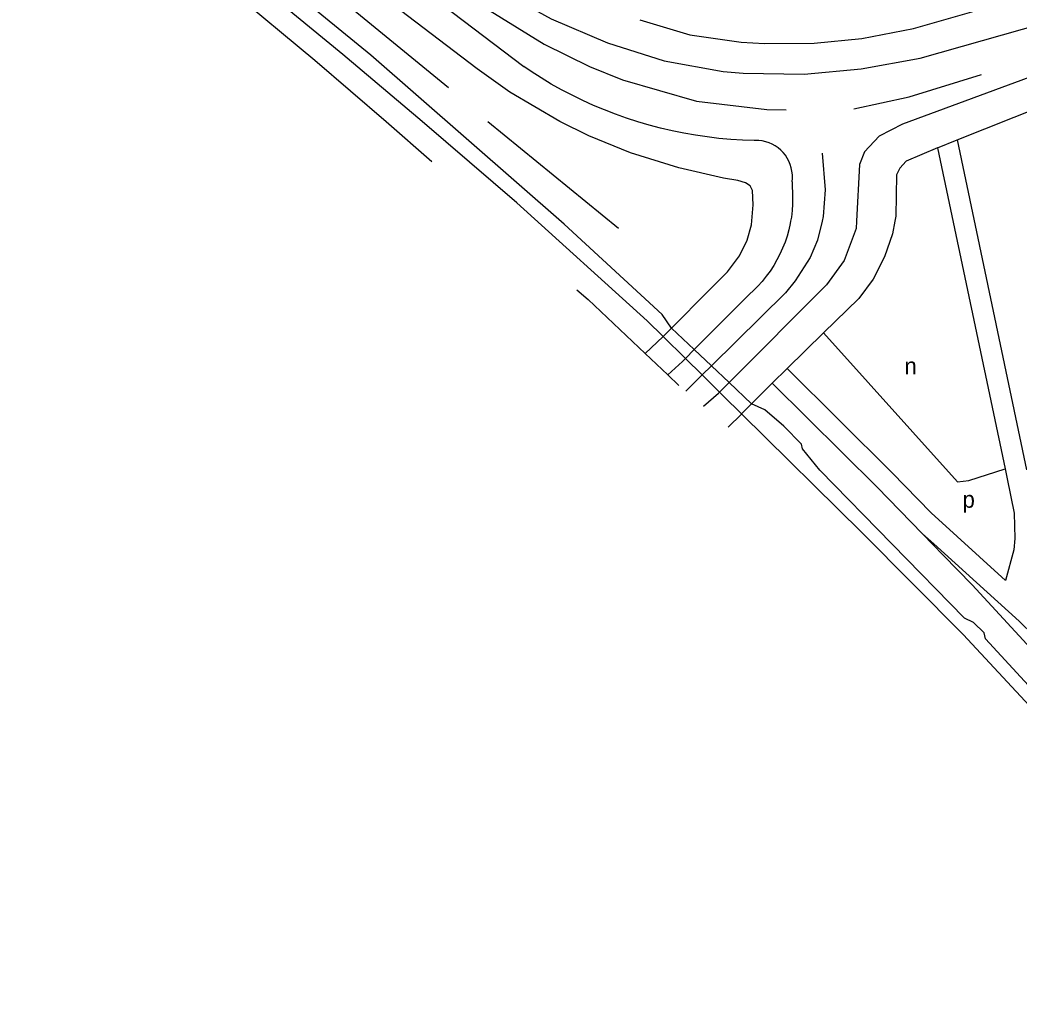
# Model space of a CAD drawing. Extents: x 163026 to 166241, y 382475 to 384501.
# Drawn here: x 164331.2 to 164570.9, y 383286.9 to 383524.4 of the extents above; entities that cross this region are included whole.
import ezdxf

# ---------------------------------------------------------------- set-up
doc = ezdxf.new("R2010")
doc.units = 0
for name, color, linetype in [('BLT_Basislijn', 7, 'Continuous'), ('BLT_Centroide', 7, 'Continuous'), ('BLT_Spoorlijn', 7, 'Continuous')]:
    doc.layers.add(name, color=color, linetype=linetype)

msp = doc.modelspace()

# ---------------------------------------------------------------- linework, layer by layer
at = {"layer": 'BLT_Basislijn'}
for p, q in [((164298.69, 383629.84), (164452.06, 383513.21)), ((164372.19, 383558.79), (164434.06, 383508.15)), ((164556.06, 383495.63), (164581.85, 383505.92)), ((164443.45, 383499.99), (164474.81, 383474.42)), ((164551.35, 383493.75), (164556.06, 383495.63)), ((164516.46, 383485.59), (164516.59, 383481.78)), ((164506.29, 383458.66), (164492.98, 383445.34)), ((164485.51, 383448.49), (164487.56, 383450.47)), ((164487.56, 383450.47), (164492.98, 383445.34)), ((164481.24, 383444.37), (164485.51, 383448.49)), ((164481.16, 383444.29), (164481.24, 383444.37)), ((164492.98, 383445.34), (164490.85, 383443.21)), ((164492.98, 383445.34), (164497.11, 383441.43)), ((164490.13, 383442.48), (164486.64, 383439.26)), ((164490.85, 383443.21), (164490.13, 383442.48)), ((164497.11, 383441.43), (164494.88, 383439.24)), ((164497.11, 383441.43), (164501.36, 383437.41)), ((164486.57, 383439.19), (164486.62, 383439.25)), ((164486.64, 383439.26), (164486.62, 383439.25)), ((164491.04, 383435.45), (164494.39, 383438.76)), ((164494.88, 383439.24), (164494.39, 383438.76)), ((164501.36, 383437.41), (164499.07, 383435.1)), ((164501.36, 383437.41), (164506.74, 383432.32)), ((164511.69, 383437.3), (164510.92, 383436.55)), ((164490.94, 383435.36), (164491.04, 383435.45)), ((164495.23, 383431.72), (164498.84, 383434.87)), ((164499.07, 383435.1), (164498.84, 383434.87)), ((164506.74, 383432.32), (164510.92, 383436.55)), ((164504.35, 383429.9), (164506.74, 383432.32)), ((164501.12, 383426.72), (164504.32, 383429.87)), ((164504.32, 383429.87), (164504.35, 383429.9)), ((164568.06, 383414.31), (164569.76, 383406.1)), ((164549.85, 383406.17), (164567.69, 383389.93))]:
    msp.add_line(p, q, dxfattribs=at)
for points in [[(164487.56, 383450.47), (164485.27, 383453.7), (164461.77, 383475.44), (164415.36, 383515.97), (164364.92, 383557.15), (164327.9, 383585.54), (164282.31, 383618.56), (164259.41, 383634.23), (164211.65, 383666.06), (164167.61, 383692.96), (164167.28, 383695.05), (164154.4, 383702.67), (164152.43, 383702), (164109.02, 383726.87), (164060.25, 383752.65), (163978.72, 383792.41), (163915.23, 383819.71), (163854.36, 383843.93), (163797.39, 383864.74), (163783.25, 383869.74), (163782.14, 383872.57), (163761.29, 383879.43), (163759.17, 383880.76)], [(164316.74, 383637.52), (164399.59, 383569.15), (164439.68, 383536.44), (164449.09, 383529.98), (164458.65, 383524.65), (164472.19, 383518.92), (164485.74, 383514.54), (164499.92, 383512), (164504.7, 383511.64), (164519.36, 383511.35), (164533, 383512.62), (164547.18, 383515.25), (164581.89, 383525.04), (164642.18, 383547.36), (164693.59, 383567.42), (164700, 383570.19), (164761.7, 383597.42), (164778.75, 383605.71), (164783.1, 383609.13), (164785.13, 383612.46), (164785.97, 383614.66), (164786.37, 383617.55)], [(164487.56, 383450.47), (164496.42, 383459.44), (164500.97, 383463.96), (164503.87, 383467.78), (164505.66, 383471.57), (164506.7, 383475.23), (164507.1, 383480.05), (164506.92, 383483.49), (164506.36, 383484.61), (164505.31, 383485.31), (164503.46, 383485.85), (164500, 383486.43), (164489.25, 383488.9), (164477.65, 383492.5), (164467.68, 383496.6), (164460.7, 383500), (164448.74, 383507.08), (164440.94, 383512.64), (164415.16, 383532.31), (164390.05, 383551.31), (164371.58, 383565.35), (164310.84, 383611.57)], [(164626.13, 383531.38), (164581.76, 383513.72), (164542.95, 383499.41), (164537.38, 383496.5), (164533.86, 383492.72), (164532.63, 383489.75), (164531.89, 383476.11)], [(164440.27, 383528.91), (164456.96, 383518.6), (164467.83, 383513.21), (164475.76, 383510.06), (164493.55, 383504.89), (164510.37, 383502.9), (164515.06, 383502.82)], [(164479.91, 383524.43), (164491.95, 383520.78), (164504.22, 383519.08), (164509.86, 383518.76), (164521.75, 383518.84), (164533.16, 383519.96), (164545.59, 383522.35), (164564.07, 383527.62)], [(164507.39, 383495.48), (164504.56, 383495.57), (164501.72, 383495.74), (164498.89, 383495.99), (164496.07, 383496.32), (164493.26, 383496.73), (164490.47, 383497.22), (164487.68, 383497.78), (164484.92, 383498.43), (164482.17, 383499.15), (164479.45, 383499.95), (164476.75, 383500.82), (164474.07, 383501.77), (164471.43, 383502.8), (164468.81, 383503.9), (164466.22, 383505.07), (164463.67, 383506.32), (164461.16, 383507.64), (164458.68, 383509.02), (164456.24, 383510.48), (164453.85, 383512.01), (164452.06, 383513.21)], [(164531.25, 383503.04), (164544.54, 383505.91), (164561.91, 383511.27)], [(164516.46, 383485.59), (164516.53, 383486.42), (164516.52, 383487.26), (164516.43, 383488.09), (164516.27, 383488.91), (164516.02, 383489.71), (164515.7, 383490.48), (164515.31, 383491.22), (164514.85, 383491.92), (164514.33, 383492.57), (164513.74, 383493.16), (164513.1, 383493.7), (164512.42, 383494.18), (164511.69, 383494.58), (164510.92, 383494.92), (164510.13, 383495.18), (164509.31, 383495.36), (164508.48, 383495.47), (164507.65, 383495.49), (164507.39, 383495.48)], [(164556.06, 383495.63), (164572.71, 383416.49)], [(164523.66, 383492.46), (164524.38, 383483.62), (164523.93, 383477.21), (164523.66, 383476.11)], [(164551.35, 383493.75), (164543.83, 383490.54), (164542.31, 383488.86), (164541.51, 383487.27), (164541.32, 383477.36), (164541.1, 383476.11)], [(164551.35, 383493.75), (164567.55, 383416.71)], [(164516.59, 383481.78), (164516.56, 383480.22), (164516.46, 383478.67), (164516.28, 383477.12), (164516.1, 383476.11)], [(164523.66, 383476.11), (164522.55, 383471.59), (164520.76, 383467.37), (164517.2, 383461.84), (164514.9, 383458.94), (164497.11, 383441.43)], [(164531.89, 383476.11), (164531.79, 383474.36), (164528.92, 383466.71), (164524.68, 383460.82), (164501.36, 383437.41)], [(164516.1, 383476.11), (164516.01, 383475.58), (164515.67, 383474.06), (164515.25, 383472.55), (164514.76, 383471.08), (164514.19, 383469.62), (164513.54, 383468.2), (164512.83, 383466.82), (164512.04, 383465.47), (164511.19, 383464.16), (164510.27, 383462.9), (164509.28, 383461.69), (164508.24, 383460.53), (164507.14, 383459.43), (164506.29, 383458.66)], [(164541.1, 383476.11), (164540.56, 383473.09), (164538.64, 383467.54), (164535.87, 383462.25), (164532.43, 383457.57), (164524.03, 383449.37)], [(164524.03, 383449.37), (164515.27, 383440.8)], [(164524.03, 383449.37), (164556.18, 383413.59), (164558.87, 383413.96), (164567.55, 383416.71)], [(164515.27, 383440.8), (164511.69, 383437.3)], [(164515.27, 383440.8), (164540.41, 383415.88), (164549.85, 383406.17)], [(164511.69, 383437.3), (164536.86, 383412.36), (164547.76, 383401.14)], [(164603.03, 383332.42), (164562.82, 383375.93), (164562.55, 383377.4), (164560, 383379.84), (164557.86, 383380.87), (164523.08, 383416.41), (164518.93, 383421.56), (164518.75, 383422.65), (164514.48, 383426.98), (164509.95, 383430.86), (164506.74, 383432.32)], [(164567.55, 383416.71), (164568.06, 383414.31)], [(164569.76, 383406.1), (164569.9, 383400.03), (164569.62, 383397.32), (164567.69, 383389.93)], [(164547.76, 383401.14), (164552.7, 383396.05), (164559.67, 383388.93)], [(164547.76, 383401.14), (164550.48, 383398.73), (164570.95, 383380.2), (164616.38, 383335.83), (164619.55, 383333.16), (164623.65, 383330.83), (164627.67, 383329.46), (164631.28, 383328.92), (164776.51, 383309.66), (164778.81, 383309.19), (164781.37, 383308.35), (164783.52, 383307.39), (164785.57, 383306.18), (164812.74, 383286.93)], [(164559.67, 383388.93), (164584.04, 383362.44)]]:
    msp.add_lwpolyline(points, dxfattribs=at)
at = {"layer": 'BLT_Spoorlijn'}
for points in [[(164427.73, 383500), (164408.7, 383516.09), (164382.43, 383537.66), (164340.68, 383570.34), (164307.34, 383595.61), (164282.42, 383613.81), (164258.52, 383630.32), (164236.28, 383645.06)], [(164236.9, 383637.8), (164254.14, 383626.61), (164275.69, 383611.78), (164294.21, 383597.97), (164312.39, 383585.5), (164337.31, 383566.64), (164366.94, 383543.39), (164381.76, 383531.59), (164401.96, 383514.75), (164419.07, 383500)], [(164419.07, 383500), (164430.03, 383490.44)], [(164485.51, 383448.49), (164481.7, 383452.24), (164450.38, 383480.55), (164427.73, 383500)], [(164464.85, 383459.68), (164467.56, 383457.3), (164481.24, 383444.37)], [(164490.85, 383443.21), (164485.51, 383448.49)], [(164481.24, 383444.37), (164486.64, 383439.26)], [(164494.88, 383439.24), (164490.85, 383443.21)], [(164486.64, 383439.26), (164489.32, 383436.74)], [(164499.07, 383435.1), (164494.88, 383439.24)], [(164500, 383434.18), (164499.07, 383435.1)], [(164504.35, 383429.9), (164500, 383434.18)], [(164588.21, 383343.97), (164557.47, 383376.96), (164533.2, 383401.45), (164504.35, 383429.9)]]:
    msp.add_lwpolyline(points, dxfattribs=at)

# ---------------------------------------------------------------- texts
at = {"layer": 'BLT_Centroide'}
for s, p in [('n', (164543.39, 383439.39)), ('p', (164557.33, 383407.39))]:
    msp.add_text(s, height=4, dxfattribs=at).set_placement(p)

doc.saveas('drawing.dxf')
